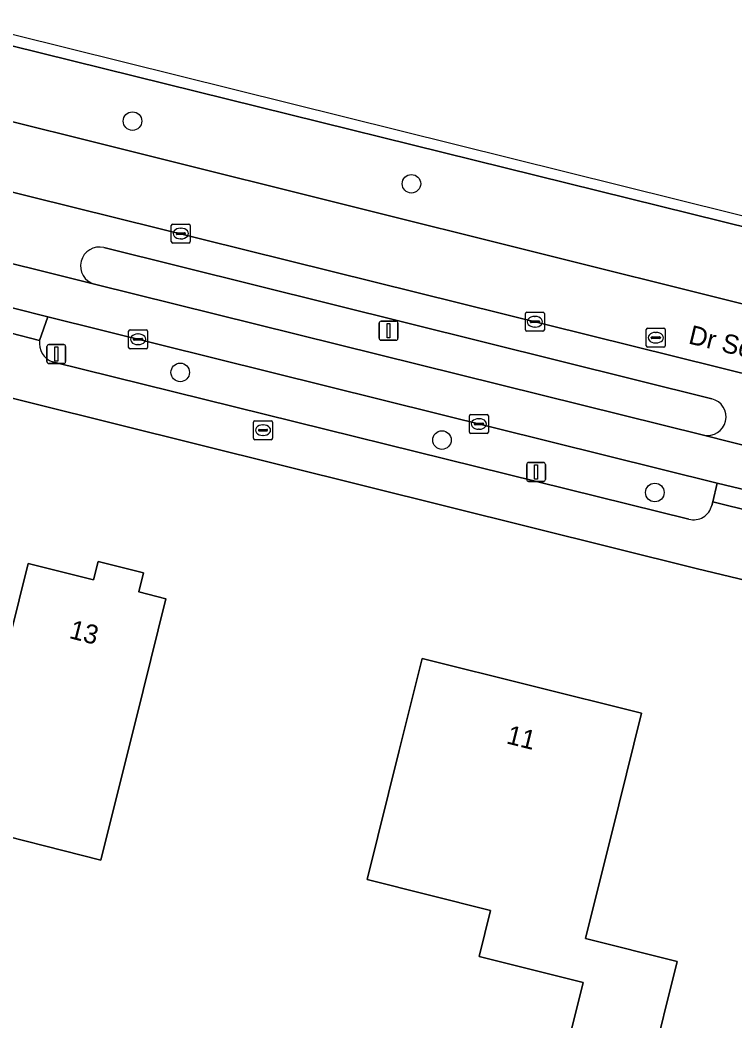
# Model space of a CAD drawing. Extents: x 161139 to 161601, y 381708 to 382245.
# Drawn here: x 161422.2 to 161459.9, y 382144.4 to 382197.2 of the extents above; entities that cross this region are included whole.
import ezdxf

# ---------------------------------------------------------------- set-up
doc = ezdxf.new("R2010")
doc.units = 0
for name, color, linetype in [('IMGEO_Berm_groen', 7, 'Continuous'), ('IMGEO_Boom', 7, 'Continuous'), ('IMGEO_Brandkraan', 7, 'Continuous'), ('IMGEO_Erf', 7, 'Continuous'), ('IMGEO_Fietspad_gesloten', 7, 'Continuous'), ('IMGEO_Kolk', 7, 'Continuous'), ('IMGEO_Lichtmast', 7, 'Continuous'), ('IMGEO_Openbare_ruimte_label', 7, 'Continuous'), ('IMGEO_Pand', 7, 'Continuous'), ('IMGEO_Pand_nummerreeks', 7, 'Continuous'), ('IMGEO_Parkeervlak_open', 7, 'Continuous'), ('IMGEO_Rijbaan_lokaal_gesloten', 7, 'Continuous'), ('IMGEO_Rioolput', 7, 'Continuous'), ('IMGEO_Voetpad_open', 7, 'Continuous')]:
    doc.layers.add(name, color=color, linetype=linetype)

msp = doc.modelspace()

# ---------------------------------------------------------------- linework, layer by layer
at = {"layer": 'IMGEO_Berm_groen'}
for points in [[(161500, 382176.547), (161460.894, 382186.197), (161420.058, 382196.306), (161417.456, 382196.964), (161416.542, 382193.184), (161418.72, 382192.635), (161459.898, 382182.379), (161500, 382172.465), (161568.862, 382155.44)], [(161458.715, 382177.254), (161426.637, 382185.233)], [(161426.145, 382183.304), (161458.283, 382175.333)], [(161423.68, 382181.579), (161423.245, 382180.339)], [(161458.712, 382171.632), (161458.766, 382171.826), (161459.001, 382172.814), (161423.68, 382181.579)], [(161423.927, 382179.199), (161457.504, 382170.904)]]:
    msp.add_lwpolyline(points, dxfattribs=at)
for centre, radius, start, end in [((161426.396, 382184.267), 0.995, 76.0062, 255.3768), ((161424.267, 382180.176), 1.035, 170.9592, 250.8203), ((161458.479, 382176.298), 0.985, 258.5026, 76.1494), ((161457.752, 382171.859), 0.987, 255.464, 346.6864)]:
    msp.add_arc(centre, radius, start, end, dxfattribs=at)
at = {"layer": 'IMGEO_Boom'}
for centre in [(161428.146, 382191.907), (161442.864, 382188.6), (161430.663, 382178.649), (161444.474, 382175.079), (161455.709, 382172.312)]:
    msp.add_circle(centre, 0.489, dxfattribs=at)
at = {"layer": 'IMGEO_Brandkraan'}
for p, q in [((161434.533, 382175.174), (161434.533, 382176.026)), ((161434.608, 382176.1), (161435.46, 382176.1)), ((161435.021, 382175.88), (161435.046, 382175.88)), ((161435.534, 382176.026), (161435.534, 382175.174)), ((161434.792, 382175.594), (161434.792, 382175.606)), ((161435.23, 382175.557), (161434.832, 382175.557)), ((161434.835, 382175.643), (161435.233, 382175.643)), ((161435.044, 382175.32), (161435.019, 382175.32)), ((161435.276, 382175.606), (161435.276, 382175.594)), ((161435.46, 382175.1), (161434.608, 382175.1))]:
    msp.add_line(p, q, dxfattribs=at)
for points in [[(161434.533, 382175.174), (161434.533, 382176.026)], [(161434.608, 382176.1), (161435.46, 382176.1)], [(161435.534, 382176.026), (161435.534, 382175.174)], [(161435.46, 382175.1), (161434.608, 382175.1)]]:
    msp.add_lwpolyline(points, dxfattribs=at)
for centre, radius, start, end in [((161434.61, 382176.024), 0.0765, 91.552, 178.448), ((161434.61, 382176.024), 0.0765, 91.552, 178.448), ((161435.458, 382176.024), 0.0765, 1.552, 88.448), ((161435.458, 382176.024), 0.0765, 1.552, 88.448), ((161434.832, 382175.603), 0.0403, 85.8775, 175.7526), ((161434.829, 382175.593), 0.0366, 178.938, 274.7102), ((161435.233, 382175.6), 0.043, 264.8664, 352.4533), ((161435.237, 382175.605), 0.0386, 1.7309, 96.639), ((161434.61, 382175.176), 0.0765, 181.552, 268.448), ((161434.61, 382175.176), 0.0765, 181.552, 268.448), ((161435.458, 382175.176), 0.0765, 271.552, 358.448), ((161435.458, 382175.176), 0.0765, 271.552, 358.448)]:
    msp.add_arc(centre, radius, start, end, dxfattribs=at)
for centre, major_axis, ratio, start_param, end_param in [((161435.02, 382175.6), (-0.387, 0.002), 0.722429, 4.712389, 7.853982), ((161435.045, 382175.6), (-0.39, 0.002), 0.717154, 1.570796, 4.712389)]:
    msp.add_ellipse(centre, major_axis=major_axis, ratio=ratio, start_param=start_param, end_param=end_param, dxfattribs=at)
at = {"layer": 'IMGEO_Erf'}
msp.add_lwpolyline([(161553.295, 382144.911), (161544.61, 382147.101), (161500, 382158.072), (161477.956, 382163.494), (161457.897, 382168.303), (161418.52, 382178.097), (161389.844, 382185.251), (161387.058, 382185.651), (161384.186, 382184.996), (161381.949, 382183.375), (161380.259, 382181.034), (161377.586, 382172.934), (161374.321, 382163.969), (161372.26, 382158.835), (161369.98, 382153.637), (161365.084, 382143.565), (161365.175, 382143.293), (161389.855, 382127.317), (161408.789, 382114.947), (161450.498, 382088.211), (161500, 382056.07), (161523.437, 382040.853), (161561.628, 382099.383), (161581.409, 382129.761)], dxfattribs=at)
for points in [[(161417.202, 382145.309), (161410.912, 382146.912), (161412.259, 382152.318), (161413.467, 382157.169), (161418.18, 382155.968), (161420.44, 382165.046), (161421.693, 382164.734), (161422.647, 382168.564), (161426.089, 382167.707), (161426.329, 382168.67), (161428.734, 382168.071), (161428.484, 382167.068), (161429.913, 382166.712), (161428.705, 382161.861), (161426.476, 382152.914), (161419.537, 382154.683)], [(161454.038, 382136.105), (161452.882, 382131.461), (161449.001, 382132.427), (161450.157, 382137.072), (161451.402, 382142.074), (161451.423, 382142.158), (161451.237, 382142.204), (161450.889, 382142.291), (161451.929, 382146.469), (161451.502, 382146.575), (161446.44, 382147.835), (161447.045, 382150.266), (161440.526, 382151.889), (161442.225, 382158.711), (161443.433, 382163.562), (161455.013, 382160.679), (161453.805, 382155.828), (161452.051, 382148.781), (161456.893, 382147.575)]]:
    msp.add_lwpolyline(points, close=True, dxfattribs=at)
at = {"layer": 'IMGEO_Fietspad_gesloten'}
for points in [[(161388.471, 382194.662), (161386.139, 382191.421), (161400.157, 382187.686), (161402.771, 382186.995), (161404.125, 382186.632), (161408.543, 382185.44), (161420.035, 382182.5), (161423.68, 382181.579), (161459.001, 382172.814), (161463.49, 382171.731), (161479.47, 382167.765), (161485.068, 382166.376)], [(161487.403, 382168.106), (161478.19, 382170.397), (161465.508, 382173.515), (161458.283, 382175.333), (161426.145, 382183.304), (161418.85, 382185.12), (161410.964, 382187.154), (161404.025, 382189.049), (161403.898, 382189.082), (161400.753, 382189.896), (161395.77, 382191.23), (161389.063, 382193.224)]]:
    msp.add_lwpolyline(points, dxfattribs=at)
at = {"layer": 'IMGEO_Kolk'}
for p, q in [((161430.192, 382185.548), (161430.192, 382186.4)), ((161430.267, 382186.474), (161431.119, 382186.474)), ((161431.193, 382186.4), (161431.193, 382185.548)), ((161430.451, 382185.968), (161430.451, 382185.98)), ((161430.889, 382185.931), (161430.491, 382185.931)), ((161430.494, 382186.017), (161430.892, 382186.017)), ((161430.68, 382186.254), (161430.705, 382186.254)), ((161430.935, 382185.98), (161430.935, 382185.968)), ((161431.119, 382185.474), (161430.267, 382185.474)), ((161430.703, 382185.694), (161430.678, 382185.694)), ((161448.879, 382180.896), (161448.879, 382181.748)), ((161448.954, 382181.822), (161449.806, 382181.822)), ((161449.367, 382181.602), (161449.392, 382181.602)), ((161449.88, 382181.748), (161449.88, 382180.896)), ((161449.138, 382181.316), (161449.138, 382181.328)), ((161449.576, 382181.279), (161449.178, 382181.279)), ((161449.181, 382181.365), (161449.579, 382181.365)), ((161449.622, 382181.328), (161449.622, 382181.316)), ((161427.94, 382179.97), (161427.94, 382180.822)), ((161428.015, 382180.896), (161428.867, 382180.896)), ((161428.428, 382180.676), (161428.453, 382180.676)), ((161428.941, 382180.822), (161428.941, 382179.97)), ((161449.806, 382180.822), (161448.954, 382180.822)), ((161449.39, 382181.042), (161449.365, 382181.042)), ((161428.199, 382180.39), (161428.199, 382180.402)), ((161428.637, 382180.353), (161428.239, 382180.353)), ((161428.242, 382180.439), (161428.64, 382180.439)), ((161428.451, 382180.116), (161428.426, 382180.116)), ((161428.683, 382180.402), (161428.683, 382180.39)), ((161428.867, 382179.896), (161428.015, 382179.896)), ((161445.925, 382175.502), (161445.925, 382176.354)), ((161446, 382176.428), (161446.852, 382176.428)), ((161446.926, 382176.354), (161446.926, 382175.502)), ((161446.184, 382175.922), (161446.184, 382175.934)), ((161446.622, 382175.885), (161446.224, 382175.885)), ((161446.227, 382175.971), (161446.625, 382175.971)), ((161446.413, 382176.208), (161446.438, 382176.208)), ((161446.668, 382175.934), (161446.668, 382175.922)), ((161446.852, 382175.428), (161446, 382175.428)), ((161446.436, 382175.648), (161446.411, 382175.648))]:
    msp.add_line(p, q, dxfattribs=at)
for points in [[(161430.192, 382185.548), (161430.192, 382186.4)], [(161430.267, 382186.474), (161431.119, 382186.474)], [(161431.193, 382186.4), (161431.193, 382185.548)], [(161431.119, 382185.474), (161430.267, 382185.474)], [(161448.879, 382180.896), (161448.879, 382181.748)], [(161448.954, 382181.822), (161449.806, 382181.822)], [(161449.88, 382181.748), (161449.88, 382180.896)], [(161427.94, 382179.97), (161427.94, 382180.822)], [(161428.015, 382180.896), (161428.867, 382180.896)], [(161428.941, 382180.822), (161428.941, 382179.97)], [(161449.806, 382180.822), (161448.954, 382180.822)], [(161428.867, 382179.896), (161428.015, 382179.896)], [(161445.925, 382175.502), (161445.925, 382176.354)], [(161446, 382176.428), (161446.852, 382176.428)], [(161446.926, 382176.354), (161446.926, 382175.502)], [(161446.852, 382175.428), (161446, 382175.428)]]:
    msp.add_lwpolyline(points, dxfattribs=at)
for centre, radius, start, end in [((161430.269, 382186.398), 0.0765, 91.552, 178.448), ((161430.269, 382186.398), 0.0765, 91.552, 178.448), ((161431.117, 382186.398), 0.0765, 1.552, 88.448), ((161431.117, 382186.398), 0.0765, 1.552, 88.448), ((161430.491, 382185.977), 0.0403, 85.8775, 175.7526), ((161430.488, 382185.967), 0.0366, 178.938, 274.7102), ((161430.892, 382185.974), 0.043, 264.8664, 352.4533), ((161430.896, 382185.979), 0.0386, 1.7309, 96.639), ((161430.269, 382185.55), 0.0765, 181.552, 268.448), ((161430.269, 382185.55), 0.0765, 181.552, 268.448), ((161431.117, 382185.55), 0.0765, 271.552, 358.448), ((161431.117, 382185.55), 0.0765, 271.552, 358.448), ((161448.956, 382181.746), 0.0765, 91.552, 178.448), ((161448.956, 382181.746), 0.0765, 91.552, 178.448), ((161449.804, 382181.746), 0.0765, 1.552, 88.448), ((161449.804, 382181.746), 0.0765, 1.552, 88.448), ((161449.178, 382181.325), 0.0403, 85.8775, 175.7526), ((161449.175, 382181.315), 0.0366, 178.938, 274.7102), ((161449.579, 382181.322), 0.043, 264.8664, 352.4533), ((161449.583, 382181.327), 0.0386, 1.7309, 96.639), ((161428.017, 382180.82), 0.0765, 91.552, 178.448), ((161428.017, 382180.82), 0.0765, 91.552, 178.448), ((161428.865, 382180.82), 0.0765, 1.552, 88.448), ((161428.865, 382180.82), 0.0765, 1.552, 88.448), ((161448.956, 382180.898), 0.0765, 181.552, 268.448), ((161448.956, 382180.898), 0.0765, 181.552, 268.448), ((161449.804, 382180.898), 0.0765, 271.552, 358.448), ((161449.804, 382180.898), 0.0765, 271.552, 358.448), ((161428.239, 382180.399), 0.0403, 85.8775, 175.7526), ((161428.236, 382180.389), 0.0366, 178.938, 274.7102), ((161428.64, 382180.396), 0.043, 264.8664, 352.4533), ((161428.644, 382180.401), 0.0386, 1.7309, 96.639), ((161428.017, 382179.972), 0.0765, 181.552, 268.448), ((161428.017, 382179.972), 0.0765, 181.552, 268.448), ((161428.865, 382179.972), 0.0765, 271.552, 358.448), ((161428.865, 382179.972), 0.0765, 271.552, 358.448), ((161446.002, 382176.352), 0.0765, 91.552, 178.448), ((161446.002, 382176.352), 0.0765, 91.552, 178.448), ((161446.85, 382176.352), 0.0765, 1.552, 88.448), ((161446.85, 382176.352), 0.0765, 1.552, 88.448), ((161446.224, 382175.931), 0.0403, 85.8775, 175.7526), ((161446.221, 382175.921), 0.0366, 178.938, 274.7102), ((161446.625, 382175.928), 0.043, 264.8664, 352.4533), ((161446.629, 382175.933), 0.0386, 1.7309, 96.639), ((161446.002, 382175.504), 0.0765, 181.552, 268.448), ((161446.002, 382175.504), 0.0765, 181.552, 268.448), ((161446.85, 382175.504), 0.0765, 271.552, 358.448), ((161446.85, 382175.504), 0.0765, 271.552, 358.448)]:
    msp.add_arc(centre, radius, start, end, dxfattribs=at)
for centre, major_axis, ratio, start_param, end_param in [((161430.679, 382185.974), (-0.387, 0.002), 0.722429, 4.712389, 7.853982), ((161430.704, 382185.974), (-0.39, 0.002), 0.717154, 1.570796, 4.712389), ((161449.366, 382181.322), (-0.387, 0.002), 0.722429, 4.712389, 7.853982), ((161449.391, 382181.322), (-0.39, 0.002), 0.717154, 1.570796, 4.712389), ((161428.427, 382180.396), (-0.387, 0.002), 0.722429, 4.712389, 7.853982), ((161428.452, 382180.396), (-0.39, 0.002), 0.717154, 1.570796, 4.712389), ((161446.412, 382175.928), (-0.387, 0.002), 0.722429, 4.712389, 7.853982), ((161446.437, 382175.928), (-0.39, 0.002), 0.717154, 1.570796, 4.712389)]:
    msp.add_ellipse(centre, major_axis=major_axis, ratio=ratio, start_param=start_param, end_param=end_param, dxfattribs=at)
at = {"layer": 'IMGEO_Lichtmast'}
for p, q in [((161441.16, 382180.448), (161441.16, 382181.248)), ((161441.16, 382181.248), (161441.16, 382180.448)), ((161441.26, 382181.348), (161442.05, 382181.348)), ((161442.05, 382181.348), (161441.26, 382181.348)), ((161442.15, 382181.248), (161442.15, 382180.448)), ((161442.15, 382180.448), (161442.15, 382181.248)), ((161423.627, 382179.216), (161423.627, 382180.016)), ((161423.627, 382180.016), (161423.627, 382179.216)), ((161423.727, 382180.116), (161424.517, 382180.116)), ((161424.517, 382180.116), (161423.727, 382180.116)), ((161424.617, 382180.016), (161424.617, 382179.216)), ((161424.617, 382179.216), (161424.617, 382180.016)), ((161442.05, 382180.348), (161441.26, 382180.348)), ((161441.26, 382180.348), (161442.05, 382180.348)), ((161424.517, 382179.116), (161423.727, 382179.116)), ((161423.727, 382179.116), (161424.517, 382179.116)), ((161448.946, 382172.995), (161448.946, 382173.795)), ((161448.946, 382173.795), (161448.946, 382172.995)), ((161449.046, 382173.895), (161449.836, 382173.895)), ((161449.836, 382173.895), (161449.046, 382173.895)), ((161449.936, 382173.795), (161449.936, 382172.995)), ((161449.936, 382172.995), (161449.936, 382173.795)), ((161449.836, 382172.895), (161449.046, 382172.895)), ((161449.046, 382172.895), (161449.836, 382172.895))]:
    msp.add_line(p, q, dxfattribs=at)
for points in [[(161441.58, 382181.223), (161441.73, 382181.223), (161441.73, 382180.473), (161441.58, 382180.473), (161441.58, 382181.223)], [(161424.047, 382179.991), (161424.197, 382179.991), (161424.197, 382179.241), (161424.047, 382179.241), (161424.047, 382179.991)], [(161449.366, 382173.77), (161449.516, 382173.77), (161449.516, 382173.02), (161449.366, 382173.02), (161449.366, 382173.77)]]:
    msp.add_lwpolyline(points, dxfattribs=at)
for centre, start, end in [((161441.26, 382181.248), 90, 180), ((161441.26, 382181.248), 90, 180), ((161442.05, 382181.248), 0, 90), ((161442.05, 382181.248), 360, 90), ((161423.727, 382180.016), 90, 180), ((161423.727, 382180.016), 90, 180), ((161424.517, 382180.016), 0, 90), ((161424.517, 382180.016), 360, 90), ((161441.26, 382180.448), 180, 270), ((161441.26, 382180.448), 180, 270), ((161442.05, 382180.448), 270, 0), ((161442.05, 382180.448), 270, 0), ((161423.727, 382179.216), 180, 270), ((161423.727, 382179.216), 180, 270), ((161424.517, 382179.216), 270, 0), ((161424.517, 382179.216), 270, 0), ((161449.046, 382173.795), 90, 180), ((161449.046, 382173.795), 90, 180), ((161449.836, 382173.795), 0, 90), ((161449.836, 382173.795), 360, 90), ((161449.046, 382172.995), 180, 270), ((161449.046, 382172.995), 180, 270), ((161449.836, 382172.995), 270, 0), ((161449.836, 382172.995), 270, 0)]:
    msp.add_arc(centre, 0.1, start, end, dxfattribs=at)
at = {"layer": 'IMGEO_Pand'}
for points in [[(161428.705, 382161.861), (161429.913, 382166.712), (161428.484, 382167.068), (161428.734, 382168.071), (161426.329, 382168.67), (161426.089, 382167.707), (161422.647, 382168.564), (161421.693, 382164.734), (161420.44, 382165.046), (161418.18, 382155.968), (161413.467, 382157.169), (161412.259, 382152.318), (161410.912, 382146.912), (161417.202, 382145.309), (161419.537, 382154.683), (161426.476, 382152.914)], [(161453.805, 382155.828), (161455.013, 382160.679), (161443.433, 382163.562), (161442.225, 382158.711), (161440.526, 382151.889), (161447.045, 382150.266), (161446.44, 382147.835), (161451.502, 382146.575), (161451.929, 382146.469), (161450.889, 382142.291), (161451.237, 382142.204), (161451.423, 382142.158), (161451.402, 382142.074), (161450.157, 382137.072), (161449.001, 382132.427), (161452.882, 382131.461), (161454.038, 382136.105), (161456.893, 382147.575), (161452.051, 382148.781)]]:
    msp.add_lwpolyline(points, close=True, dxfattribs=at)
at = {"layer": 'IMGEO_Parkeervlak_open'}
for points in [[(161502.587, 382168.125), (161500, 382168.766), (161459.102, 382178.908), (161420.449, 382188.487), (161415.442, 382189.785), (161412.878, 382190.505)], [(161418.85, 382185.12), (161426.145, 382183.304)], [(161426.637, 382185.233), (161458.715, 382177.254)], [(161458.283, 382175.333), (161465.508, 382173.515)]]:
    msp.add_lwpolyline(points, dxfattribs=at)
for centre, radius, start, end in [((161426.396, 382184.267), 0.995, 76.0062, 255.3768), ((161458.479, 382176.298), 0.985, 258.5026, 76.1494)]:
    msp.add_arc(centre, radius, start, end, dxfattribs=at)
at = {"layer": 'IMGEO_Rijbaan_lokaal_gesloten'}
for points in [[(161562.018, 382161.64), (161415.973, 382197.911), (161384.398, 382213.493), (161381.617, 382214.866), (161356.708, 382243.113)], [(161374.664, 382217.069), (161378.836, 382213.986), (161381.705, 382212.177), (161383.113, 382211.438), (161385.647, 382210.252), (161389.368, 382208.652), (161392.021, 382207.47), (161392.131, 382207.421), (161400.173, 382203.726), (161402.655, 382202.572), (161402.834, 382202.489), (161404.051, 382201.98), (161404.678, 382201.717), (161413.629, 382198.305), (161416.752, 382197.147), (161417.456, 382196.964), (161420.058, 382196.306), (161460.894, 382186.197), (161500, 382176.547)], [(161371.295, 382209.7), (161379.73, 382204.16), (161385.013, 382201.164), (161389.691, 382198.806), (161397.081, 382195.854), (161402.036, 382194.12), (161402.198, 382194.055), (161405.248, 382192.835), (161406.546, 382192.371), (161409.616, 382191.449), (161412.637, 382190.575), (161412.768, 382190.537), (161412.878, 382190.505), (161415.442, 382189.785), (161420.449, 382188.487), (161459.102, 382178.908), (161500, 382168.766), (161502.587, 382168.125), (161571.771, 382151.019), (161574.719, 382150.267), (161575.117, 382154.078)], [(161568.862, 382155.44), (161500, 382172.465), (161459.898, 382182.379), (161418.72, 382192.635), (161416.542, 382193.184)]]:
    msp.add_lwpolyline(points, dxfattribs=at)
at = {"layer": 'IMGEO_Rioolput'}
for p, q in [((161455.257, 382180.054), (161455.257, 382180.906)), ((161455.332, 382180.98), (161456.184, 382180.98)), ((161455.745, 382180.76), (161455.77, 382180.76)), ((161456.258, 382180.906), (161456.258, 382180.054)), ((161455.516, 382180.474), (161455.516, 382180.486)), ((161455.954, 382180.437), (161455.556, 382180.437)), ((161455.559, 382180.523), (161455.957, 382180.523)), ((161455.768, 382180.2), (161455.743, 382180.2)), ((161456, 382180.486), (161456, 382180.474)), ((161456.184, 382179.98), (161455.332, 382179.98))]:
    msp.add_line(p, q, dxfattribs=at)
for points in [[(161455.257, 382180.054), (161455.257, 382180.906)], [(161455.332, 382180.98), (161456.184, 382180.98)], [(161456.258, 382180.906), (161456.258, 382180.054)], [(161456.184, 382179.98), (161455.332, 382179.98)]]:
    msp.add_lwpolyline(points, dxfattribs=at)
for centre, radius, start, end in [((161455.334, 382180.904), 0.0765, 91.552, 178.448), ((161455.334, 382180.904), 0.0765, 91.552, 178.448), ((161456.182, 382180.904), 0.0765, 1.552, 88.448), ((161456.182, 382180.904), 0.0765, 1.552, 88.448), ((161455.334, 382180.056), 0.0765, 181.552, 268.448), ((161455.334, 382180.056), 0.0765, 181.552, 268.448), ((161455.556, 382180.483), 0.0403, 85.8775, 175.7526), ((161455.553, 382180.473), 0.0366, 178.938, 274.7102), ((161455.957, 382180.48), 0.043, 264.8664, 352.4533), ((161455.961, 382180.485), 0.0386, 1.7309, 96.639), ((161456.182, 382180.056), 0.0765, 271.552, 358.448), ((161456.182, 382180.056), 0.0765, 271.552, 358.448)]:
    msp.add_arc(centre, radius, start, end, dxfattribs=at)
for centre, major_axis, ratio, start_param, end_param in [((161455.744, 382180.48), (-0.387, 0.002), 0.722429, 4.712389, 7.853982), ((161455.769, 382180.48), (-0.39, 0.002), 0.717154, 1.570796, 4.712389)]:
    msp.add_ellipse(centre, major_axis=major_axis, ratio=ratio, start_param=start_param, end_param=end_param, dxfattribs=at)
at = {"layer": 'IMGEO_Voetpad_open'}
for points in [[(161378.971, 382187.245), (161387.058, 382185.651), (161389.844, 382185.251), (161418.52, 382178.097), (161457.897, 382168.303), (161477.956, 382163.494), (161500, 382158.072), (161544.61, 382147.101), (161553.295, 382144.911), (161577.621, 382138.939), (161579.137, 382138.37), (161582.049, 382137.272), (161581.211, 382138.152), (161576.782, 382142.804)], [(161423.245, 382180.339), (161420.225, 382181.103), (161419.997, 382180.199), (161407.86, 382183.171), (161408.169, 382184.367), (161403.727, 382185.497)], [(161457.504, 382170.904), (161423.927, 382179.199)], [(161463.131, 382170.447), (161463.163, 382170.733), (161458.766, 382171.826), (161458.712, 382171.632)]]:
    msp.add_lwpolyline(points, dxfattribs=at)
for points in [[(161423.68, 382181.579), (161420.035, 382182.5), (161420.271, 382181.292), (161420.225, 382181.103), (161423.245, 382180.339)], [(161458.766, 382171.826), (161463.163, 382170.733), (161463.49, 382171.731), (161459.001, 382172.814)]]:
    msp.add_lwpolyline(points, close=True, dxfattribs=at)
for centre, radius, start, end in [((161424.267, 382180.176), 1.035, 170.9592, 250.8203), ((161457.752, 382171.859), 0.987, 255.464, 346.6864)]:
    msp.add_arc(centre, radius, start, end, dxfattribs=at)

# ---------------------------------------------------------------- texts
at = {"layer": 'IMGEO_Openbare_ruimte_label'}
msp.add_text('Dr Schaepmanlaan', height=1, rotation=346.3528, dxfattribs=at).set_placement((161457.435, 382180.183))
at = {"layer": 'IMGEO_Pand_nummerreeks'}
for s, rotation, p in [('13', 345.7006, (161424.757, 382164.642)), ('11', 346.0198, (161447.827, 382159.087))]:
    msp.add_text(s, height=1, rotation=rotation, dxfattribs=at).set_placement(p)

doc.saveas('drawing.dxf')
